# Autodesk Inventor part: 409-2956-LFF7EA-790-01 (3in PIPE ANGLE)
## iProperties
Shininess: 64.0
Angle Display Precision: 2
Document Length Units: 11272
Document Angle Units: 11279
Document Time Units: 11290
Document Mass Units: 11286
Document Length Units Precision: 3
Document Angle Units Precision: 2
Compacted: True
Created: 2002-04
Part Number: 409-2956-LFF7EA-790-01 (3in PIPE ANGLE)
Description: 4" PIPE MOUNT ANGLE
Document SubType Name: Modeling
Designer: S. Boerckel
Mass: 826.332 g
Surface Area: 360.435 cm^2
Volume: 105.265 cm^3
Density: 7.85 g/cm^3
Cost Center: 2 x 2 x 1/4 ANGLE
Material: ASTM A36
Engineer: S. Boerckel
User Status: SAW/PUNCH
Density: 0.0
Volumn: 0.0
Area: 0.0
PropertySet Name: Model Information
Control State: 0
Master: False
Checked Out: False
length: 7.000 in
SMR: =<COST CENTER> - <MATERIAL>
Author: S. Boerckel
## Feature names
1. Extrusion1
2. Hole1
